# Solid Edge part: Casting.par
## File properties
Author: Vicky Raina
Template: Normal.par
Last saved by: Administrator
Revision: 9
Application: Solid Edge
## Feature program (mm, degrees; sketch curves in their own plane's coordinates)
sketch for "unnamed Protrusion 1" plane through (0, 0, 0) normal (0, -1, 0) x-axis (1, 0, 0)
  line (0, 0) -> (0, 0)
  line (-104, 0) -> (104, 0)
  line (104, 0) -> (100, 14)
  line (100, 14) -> (-100, 14)
  line (-100, 14) -> (-104, 0)
  dimension (linear) = 104
  dimension (linear) = 104
extrude "unnamed Protrusion 1" add finite 46 symmetric
sketch for "unnamed Protrusion 2" plane through (0, 0, 0) normal (0, 0, 1) x-axis (1, 0, 0)
  line (-48.8569, 23) -> (48.8569, 23)
  arc centre (0, 0) radius 54 from (48.8569, 23) to (48.8569, -23) cw
  line (-48.8569, -23) -> (48.8569, -23)
  arc centre (0, 0) radius 54 from (-48.8569, -23) to (-48.8569, 23) cw
extrude "unnamed Protrusion 2" add finite 68 along +normal
sketch for "unnamed Cutout 1" plane through (0, 0, 0) normal (0, -1, 0) x-axis (1, 0, 0)
  line (24, 52) -> (24, 48)
  line (28, 52) -> (24, 52)
  line (28, 68) -> (28, 52)
  line (-28, 68) -> (28, 68)
  line (-28, 52) -> (-28, 68)
  line (-24, 52) -> (-28, 52)
  line (-24, 48) -> (-24, 52)
  arc centre (0, 48) radius 24 from (24, 48) to (-24, 48) cw
extrude "unnamed Cutout 1" cut finite 46 symmetric
chamfer "unnamed Chamfer 1"
fillet "unnamed Round 1"
sketch for "unnamed Hole 1" plane through (-41, 0, 68) normal (0, 0, 1) x-axis (0, 1, 0)
  hole centre (0, -80) bore radius 6
hole "unnamed Hole 1" through
sketch for "unnamed Cutout 2" plane through (0, 0, 0) normal (0, 0, 1) x-axis (1, 0, 0)
  line (23.9671, 14) -> (23.9671, -14)
  line (23.9671, -14) -> (51.9671, -14)
  line (51.9671, -14) -> (51.9671, 14)
  line (51.9671, 14) -> (23.9671, 14)
extrude "unnamed Cutout 2" cut finite 12 along +normal
sketch for "unnamed Cutout 3" plane through (0, 0, 0) normal (0, 0, 1) x-axis (1, 0, 0)
  line (71, 6) -> (71, -6)
  line (71, -6) -> (91, -6)
  line (91, -6) -> (91, 6)
  line (91, 6) -> (71, 6)
extrude "unnamed Cutout 3" cut through along +normal
fillet "unnamed Round 2"
mirror "unnamed Mirror 1" of "unnamed Round 2", "unnamed Cutout 3", "unnamed Cutout 2", "unnamed Hole 1"
pattern "unnamed Pattern 1"
sketch for "unnamed Cutout 4" plane through (0, 0, 0) normal (0, 0, 1) x-axis (1, 0, 0)
  line (-97.5, 20) -> (-97.5, -20)
  line (-97.5, -20) -> (97.5, -20)
  line (97.5, -20) -> (97.5, 20)
  line (97.5, 20) -> (-97.5, 20)
extrude "unnamed Cutout 4" cut finite 2 along +normal
sketch for "unnamed Hole 2" plane through (-41, 0, 68) normal (0, 0, 1) x-axis (1, 0, 0)
  hole centre (41, 0) bore radius 4
hole "unnamed Hole 2" finite
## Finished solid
Body 1: solid body, 53 faces, 134 edges, 84 vertices.
  Faces by surface: plane 39, cylinder 10, cone 2, torus 2
  Edges by curve: line 106, circle 23, intersection 5
Bounding box of the edges (mm; curved faces can reach further): 208.000 x 46.000 x 68.000, from (-104, -23, 0) to (104, 23, 68).
Cylindrical faces by radius (mm): R4 x1, R6 x6, R24 x1, R54 x2
Conical faces (half-angle, radius in mm at the cone's reference point): 45 deg R24 x1, 45 deg R26 x1
Toroidal faces (ring radius, tube radius in mm): R62 r8 x2
Planar faces by outward normal: +x 5, +y 6, +z 7, -x 5, -y 6, -z 4, oblique 6
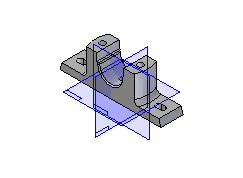
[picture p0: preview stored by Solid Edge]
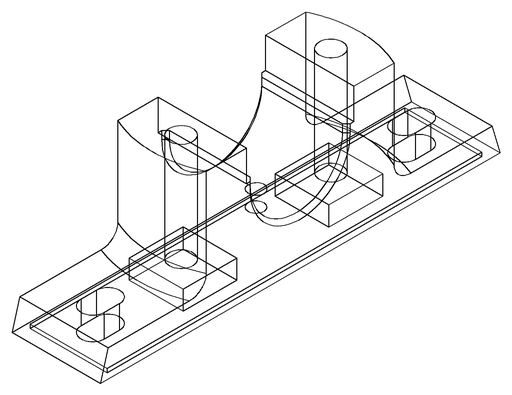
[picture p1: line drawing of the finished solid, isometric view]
